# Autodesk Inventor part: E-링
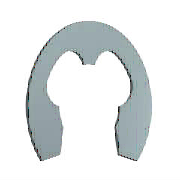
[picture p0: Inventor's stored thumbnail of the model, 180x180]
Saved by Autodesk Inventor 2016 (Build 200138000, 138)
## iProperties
IsCustomPart: 1
Created: 2012-02
Part Number: E-링
Material: 강철, 연강
Description: 일반용 테이퍼 및 줄어든 횡단면 리테이닝 링 - E-링 외부 시리즈 3CM1 리테이닝 링
Document SubType Name: Modeling
Standard: ANSI B27.7
Designer: mduedu
Standard Revision: 1999
Standards Organization: ANSI
Language: ko-KR
Size Designation: 6
Categories: <MemberInstance><Categories><Category DisplayName="샤프트 부품" InternalName="7f7aeb1f-a693-4053-b835-cee3144e0d98" Mnemonic="SHFT"><Category DisplayName="써클립" Inter
Density: 1 g/cm^3
Appearance: 파란색 - 벽 페인트 - 광택
Author: mduedu
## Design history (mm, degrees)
sketch "스케치1"
  geometry: L1 (-0.485, 0.024)-(0, 0.024) reference; L2 (-3.206, 0)-(3.486, 0) reference; L3 (-2.223, -3.946)-(2.223, -3.946); L4 (0, 1.949)-(0, -3.479) reference; L5 (-2.91, -2.006)-(-2.435, -2.006); L6 (-0.485, -0.066)-(-0.485, 0.405); L7 (0, 2.574)-(2.53, 2.574); L8 (-2.223, -3.946)-(-3.022, -6.291); L9 (0, -0.551)-(-1.278, -0.551); L10 (2.223, -3.946)-(3.022, -6.291); L11 (2.91, -2.006)-(2.435, -2.006); L12 (0.485, -0.066)-(0.485, 0.405); C1 r 3 at (0, -2.976); A1 r 2.425 centre (0, -2.976) between (-2.297, -2.199) and (-2.223, -3.946); A2 r 0.485 centre (0, -0.066) between (-0.485, -0.066) and (0.485, -0.066); A3 r 5.55 centre (0, -2.976) between (4.27, -6.521) and (-4.27, -6.521); A4 r 3.88 centre (0, -2.976) between (-0.97, 0.78) and (-3.424, -1.15); A5 r 0.388 centre (-0.873, 0.405) between (-0.485, 0.405) and (-0.97, 0.78); A6 r 0.582 centre (-2.91, -1.424) between (-3.424, -1.15) and (-2.91, -2.006); A7 r 0.145 centre (-2.435, -2.152) between (-2.297, -2.199) and (-2.435, -2.006); A8 r 0.727 centre (-3.711, -6.057) between (-4.27, -6.521) and (-3.022, -6.291); A9 r 0.727 centre (3.711, -6.057) between (3.022, -6.291) and (4.27, -6.521); A10 r 2.425 centre (0, -2.976) between (2.223, -3.946) and (2.297, -2.199); A11 r 0.145 centre (2.435, -2.152) between (2.435, -2.006) and (2.297, -2.199); A12 r 0.582 centre (2.91, -1.424) between (2.91, -2.006) and (3.424, -1.15); A13 r 3.88 centre (0, -2.976) between (3.424, -1.15) and (0.97, 0.78); A14 r 0.388 centre (0.873, 0.405) between (0.97, 0.78) and (0.485, 0.405); 1 further point
  constraints: 30 point on circle, 20 end point, 15 centre point, 13 symmetric about line, 12 tangent, 8 point on line, 4 parallel, 2 coincident, 2 horizontal, 1 concentric, 1 perpendicular, 1 vertical alignment, 9 other
  dimensions: "d0" = 6 diameter of C1 (= WD); "d3" = 0.97 distance from line of A1.centre L3 (= 0.2 x ND); "d4" = 0.485 radius of A2 (= 0.1 x ND); "d5" = 11.1 diameter of A3 (= SD2); "d8" = 3.88 radius of A4 (= 0.8 x ND); "d9" = 0.97 distance from line of A1.centre L5 (= 0.2 x ND); "d10" = 0.388 radius of A5 (= 0.08 x ND); "d11" = 0.582 radius of A6 (= 0.12 x ND); "d12" = 0.1455 radius of A7 (= 0.03 x ND); "d13" = 0.7275 radius of A8 (= 0.15 x ND); "d14" = 2.425 distance from line of A1.centre L9 (= 0.5 x ND); "d15" = 2.425 radius of A1 (= 0.5 x ND)
extrude "본체" new body sketch "스케치1" distance "d16" = 0.6 (= SD); taper "d17" = 0 deg
workaxis "Work Axis1"
workaxis "Work Axis2"
workplane "Work Plane1"
body "Solid1"
other parameters: "ND" = 4.85 [user parameter; used in 14 equation terms], "SD" = 0.6 [user parameter; used in 1 equation term], "WD" = 6 (= WDMIN) [user parameter; used in 1 equation term], "d1" = 7.76 (= 1.6 x ND), "d2" = 4.85 (= ND), "SD2" = 11.1 [user parameter; used in 1 equation term], "d6" = 4.85 (= ND), "d7" = 0.7275 (= 0.15 x ND), "d18" = 0, "d19" = 0, "d27" = 0, "d28" = 0, "WDMIN" = 6 [user parameter; used in 1 equation term], "SNB" = 0.7 [user parameter], "WDMAX" = 7 [user parameter], "BUBRMI" = 1.2 [user parameter]
